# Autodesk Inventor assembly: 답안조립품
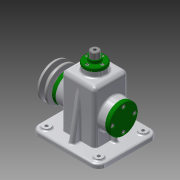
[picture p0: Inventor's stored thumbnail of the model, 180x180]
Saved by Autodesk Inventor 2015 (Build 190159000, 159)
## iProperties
Created: 2016-02
Part Number: 답안조립품
Document SubType Name: Assembly
Designer: Administrator
Author: Administrator
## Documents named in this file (19)
- C:\Users\Administrator\Desktop\460219V1011\답안조립품.iam
- C:\Users\Administrator\Desktop\460219V1011\본체.ipt
- C:\Users\Administrator\Desktop\460219V1011\V-벨트풀리.ipt
- C:\Users\Administrator\Desktop\460219V1011\고정핀.ipt
- C:\Users\Administrator\Desktop\460219V1011\뒤커버.ipt
- C:\Users\Administrator\Desktop\460219V1011\링크.ipt
- C:\Users\Administrator\Desktop\460219V1011\멈춤링 6 x 5.ipt
- C:\Users\Administrator\Desktop\460219V1011\멈춤링 15 x 1.ipt
- C:\Users\Administrator\Desktop\460219V1011\베어링 15 x 35 x 11.ipt
- C:\Users\Administrator\Desktop\460219V1011\볼트 M3 x 8.ipt
- C:\Users\Administrator\Desktop\460219V1011\볼트 M4 x 10.ipt
- C:\Users\Administrator\Desktop\460219V1011\볼트 M6 x 12.ipt
- C:\Users\Administrator\Desktop\460219V1011\상부부시.ipt
- C:\Users\Administrator\Desktop\460219V1011\슬라이드바.ipt
- C:\Users\Administrator\Desktop\460219V1011\앞커버.ipt
- C:\Users\Administrator\Desktop\460219V1011\오일실 15 25 7.ipt
- C:\Users\Administrator\Desktop\460219V1011\와셔.ipt
- C:\Users\Administrator\Desktop\460219V1011\키 5 x 5 x 14.ipt
- C:\Users\Administrator\Desktop\460219V1011\편심축.ipt
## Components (15 placed, 5 different names)
1. V-벨트풀리:1
2. 고정핀:1
3. ISO 4018 M6 x 12:1
4. ISO 4762 M4 x 10:2
5. ISO 4762 M4 x 10:3
6. ISO 4762 M4 x 10:4
7. ISO 4762 M4 x 10:5
8. ISO 4762 M4 x 10:1
9. ISO 4762 M4 x 10:6
10. ISO 4762 M4 x 10:7
11. ISO 4762 M4 x 10:8
12. ISO 4762 M3 x 8:1
13. ISO 4762 M3 x 8:2
14. ISO 4762 M3 x 8:3
15. ISO 4762 M3 x 8:4
